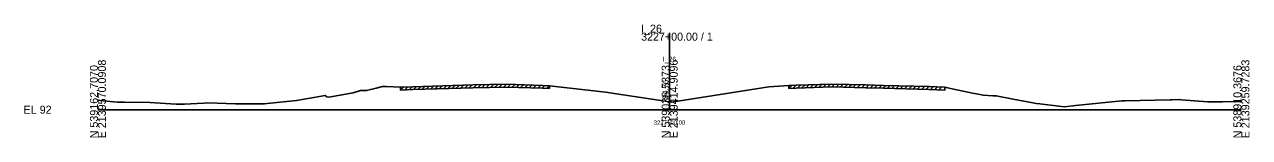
# Model space of a CAD drawing. Extents: x -13101 to 4803, y -924 to 22390.
# Drawn here: x 1974.3 to 2402.8, y 13490.3 to 13529.8 of the extents above; entities that cross this region are included whole.
import ezdxf

# ---------------------------------------------------------------- set-up
doc = ezdxf.new("R2010")
doc.units = 0
for name, color, linetype in [('RD_GPK_XS_Cell', 7, 'Continuous'), ('RD_XS_ExGround', 7, 'Continuous'), ('RD_XS_ExPaveRet', 7, 'Continuous'), ('RD_XS_TX_Baseline', 7, 'Continuous'), ('RD_XS_TX_Elev_EX', 7, 'Continuous'), ('RD_XS_TX_Station', 7, 'Continuous')]:
    doc.layers.add(name, color=color, linetype=linetype)

msp = doc.modelspace()

# ---------------------------------------------------------------- linework, layer by layer
at = {"layer": 'RD_GPK_XS_Cell'}
for p, q in [((2200, 13500), (2200, 13526.91)), ((2000, 13500), (2200, 13500)), ((2200, 13500), (2400, 13500))]:
    msp.add_line(p, q, dxfattribs=at)
at = {"layer": 'RD_XS_ExGround'}
msp.add_lwpolyline([(2000, 13503.31), (2001.86, 13503.15), (2006.89, 13502.68), (2008.09, 13502.58), (2009.24, 13502.58), (2018.1, 13502.49), (2027.36, 13501.97), (2028.1, 13501.94), (2030.24, 13501.98), (2034.71, 13502.17), (2037.13, 13502.3), (2038.42, 13502.38), (2048.11, 13502.09), (2051.17, 13502.08), (2058.31, 13502.07), (2059.16, 13502.16), (2069.47, 13503.26), (2077.55, 13504.6), (2079.48, 13504.91), (2080.09, 13504.47), (2080.79, 13504.42), (2089.34, 13505.91), (2091.83, 13506.73), (2093.98, 13506.7), (2097.34, 13507.55), (2099.5, 13508.1), (2100.81, 13508.07), (2105.87, 13507.88), (2110.12, 13508.02), (2131.16, 13508.65), (2142.93, 13508.93), (2155.49, 13508.49), (2157.95, 13508.37), (2177.52, 13506.09), (2200, 13502.76), (2200.68, 13502.65), (2234.67, 13507.96), (2241.7, 13508.44), (2244.27, 13508.52), (2256.78, 13508.97), (2268.67, 13508.66), (2274.77, 13508.51), (2290.75, 13508.1), (2296.29, 13507.83), (2297.23, 13507.66), (2305.91, 13505.83), (2307.91, 13505.45), (2309.7, 13505.07), (2313, 13504.89), (2314.24, 13504.86), (2320.22, 13503.68), (2327.09, 13502.37), (2328.22, 13502.18), (2329.49, 13502.03), (2337.09, 13501.16), (2338.1, 13501.04), (2342, 13501.44), (2358.23, 13503.14), (2359.32, 13503.14), (2375.09, 13503.47), (2375.71, 13503.46), (2378.24, 13503.53), (2378.97, 13503.51), (2388.25, 13502.75), (2389.63, 13502.74), (2393.45, 13502.81), (2400, 13502.92)], dxfattribs=at)
at = {"layer": 'RD_XS_ExPaveRet'}
for p, q in [((2105.87, 13506.88), (2106.91, 13507.92)), ((2105.87, 13506.88), (2105.87, 13507.88)), ((2107.37, 13506.93), (2108.41, 13507.96)), ((2108.87, 13506.98), (2109.91, 13508.01)), ((2110.12, 13507.02), (2131.16, 13507.65)), ((2110.37, 13507.03), (2111.41, 13508.06)), ((2111.87, 13507.07), (2112.91, 13508.1)), ((2113.37, 13507.12), (2114.41, 13508.15)), ((2114.87, 13507.16), (2115.91, 13508.19)), ((2116.37, 13507.21), (2117.41, 13508.24)), ((2117.87, 13507.25), (2118.91, 13508.28)), ((2119.37, 13507.3), (2120.41, 13508.33)), ((2120.87, 13507.34), (2121.91, 13508.38)), ((2122.37, 13507.39), (2123.41, 13508.42)), ((2123.87, 13507.43), (2124.91, 13508.47)), ((2125.37, 13507.48), (2126.41, 13508.51)), ((2126.87, 13507.53), (2127.91, 13508.56)), ((2128.37, 13507.57), (2129.41, 13508.6)), ((2129.87, 13507.62), (2130.91, 13508.65)), ((2131.16, 13507.65), (2142.93, 13507.93)), ((2131.37, 13507.66), (2132.4, 13508.68)), ((2132.87, 13507.69), (2133.9, 13508.72)), ((2134.37, 13507.73), (2135.4, 13508.75)), ((2135.87, 13507.76), (2136.9, 13508.79)), ((2137.37, 13507.8), (2138.4, 13508.82)), ((2138.87, 13507.83), (2139.9, 13508.86)), ((2140.37, 13507.87), (2141.4, 13508.89)), ((2141.87, 13507.9), (2142.9, 13508.93)), ((2142.93, 13507.93), (2155.49, 13507.49)), ((2143.37, 13507.91), (2144.34, 13508.88)), ((2144.87, 13507.86), (2145.84, 13508.82)), ((2146.37, 13507.81), (2147.34, 13508.77)), ((2147.87, 13507.75), (2148.84, 13508.72)), ((2149.37, 13507.7), (2150.34, 13508.67)), ((2150.87, 13507.65), (2151.84, 13508.62)), ((2152.37, 13507.6), (2153.34, 13508.56)), ((2153.87, 13507.55), (2154.84, 13508.51)), ((2155.37, 13507.49), (2156.33, 13508.45)), ((2155.49, 13507.49), (2157.95, 13507.37)), ((2156.87, 13507.42), (2157.83, 13508.38)), ((2157.95, 13508.37), (2157.95, 13507.37)), ((2241.7, 13507.44), (2242.73, 13508.47)), ((2241.7, 13507.44), (2241.7, 13508.44)), ((2241.7, 13507.44), (2244.27, 13507.52)), ((2243.2, 13507.49), (2244.23, 13508.52)), ((2244.27, 13507.52), (2256.78, 13507.97)), ((2244.7, 13507.54), (2245.74, 13508.58)), ((2246.2, 13507.59), (2247.24, 13508.63)), ((2247.7, 13507.65), (2248.74, 13508.68)), ((2249.2, 13507.7), (2250.24, 13508.74)), ((2250.7, 13507.75), (2251.74, 13508.79)), ((2252.2, 13507.81), (2253.24, 13508.84)), ((2253.7, 13507.86), (2254.74, 13508.9)), ((2255.2, 13507.91), (2256.24, 13508.95)), ((2256.7, 13507.97), (2257.68, 13508.95)), ((2256.78, 13507.97), (2268.67, 13507.66)), ((2258.2, 13507.93), (2259.17, 13508.91)), ((2259.7, 13507.9), (2260.67, 13508.87)), ((2261.2, 13507.86), (2262.17, 13508.83)), ((2262.7, 13507.82), (2263.67, 13508.79)), ((2264.2, 13507.78), (2265.17, 13508.75)), ((2265.7, 13507.74), (2266.67, 13508.72)), ((2267.2, 13507.7), (2268.17, 13508.68)), ((2268.67, 13507.66), (2274.77, 13507.51)), ((2268.7, 13507.66), (2269.68, 13508.64)), ((2270.2, 13507.63), (2271.18, 13508.6)), ((2271.7, 13507.59), (2272.68, 13508.56)), ((2273.2, 13507.55), (2274.18, 13508.53)), ((2274.7, 13507.51), (2275.67, 13508.49)), ((2274.77, 13507.51), (2290.75, 13507.1)), ((2276.2, 13507.47), (2277.17, 13508.45)), ((2277.7, 13507.44), (2278.67, 13508.41)), ((2279.2, 13507.4), (2280.17, 13508.37)), ((2280.7, 13507.36), (2281.67, 13508.33)), ((2282.2, 13507.32), (2283.17, 13508.29)), ((2283.7, 13507.28), (2284.67, 13508.25)), ((2285.2, 13507.24), (2286.17, 13508.22)), ((2286.7, 13507.2), (2287.67, 13508.18)), ((2288.2, 13507.16), (2289.17, 13508.14)), ((2289.7, 13507.12), (2290.67, 13508.1)), ((2291.2, 13507.08), (2292.15, 13508.03)), ((2292.7, 13507), (2293.65, 13507.96)), ((2294.2, 13506.93), (2295.15, 13507.88)), ((2296.29, 13507.83), (2296.29, 13506.83)), ((2105.87, 13506.88), (2110.12, 13507.02)), ((2290.75, 13507.1), (2296.29, 13506.83))]:
    msp.add_line(p, q, dxfattribs=at)

# ---------------------------------------------------------------- texts
at = {"layer": 'RD_GPK_XS_Cell'}
for s, p in [('I_26', (2190, 13526.91)), ('3227+00.00 / 1', (2190, 13524.11)), ('EL 92', (1974, 13498.6))]:
    msp.add_text(s, height=2.8, dxfattribs=at).set_placement(p)
for s, p in [('E 2139570.0908', (2002.8, 13490)), ('E 2139414.9096', (2202.8, 13490)), ('E 2139259.7283', (2402.8, 13490)), ('N 539162.7070', (2000, 13490)), ('N 539036.5373', (2200, 13490)), ('N 538910.3676', (2400, 13490))]:
    msp.add_text(s, height=2.8, rotation=90, dxfattribs=at).set_placement(p)
at = {"layer": 'RD_XS_TX_Baseline'}
msp.add_text('I_26', height=1.75, dxfattribs=at).set_placement((2197.6, 13516.76))
at = {"layer": 'RD_XS_TX_Elev_EX'}
msp.add_text('94.76', height=2, rotation=90, dxfattribs=at).set_placement((2199.5, 13503.76))
at = {"layer": 'RD_XS_TX_Station'}
msp.add_text('3227+00.00', height=1.5, dxfattribs=at).set_placement((2194.44, 13494.76))

doc.saveas('drawing.dxf')
